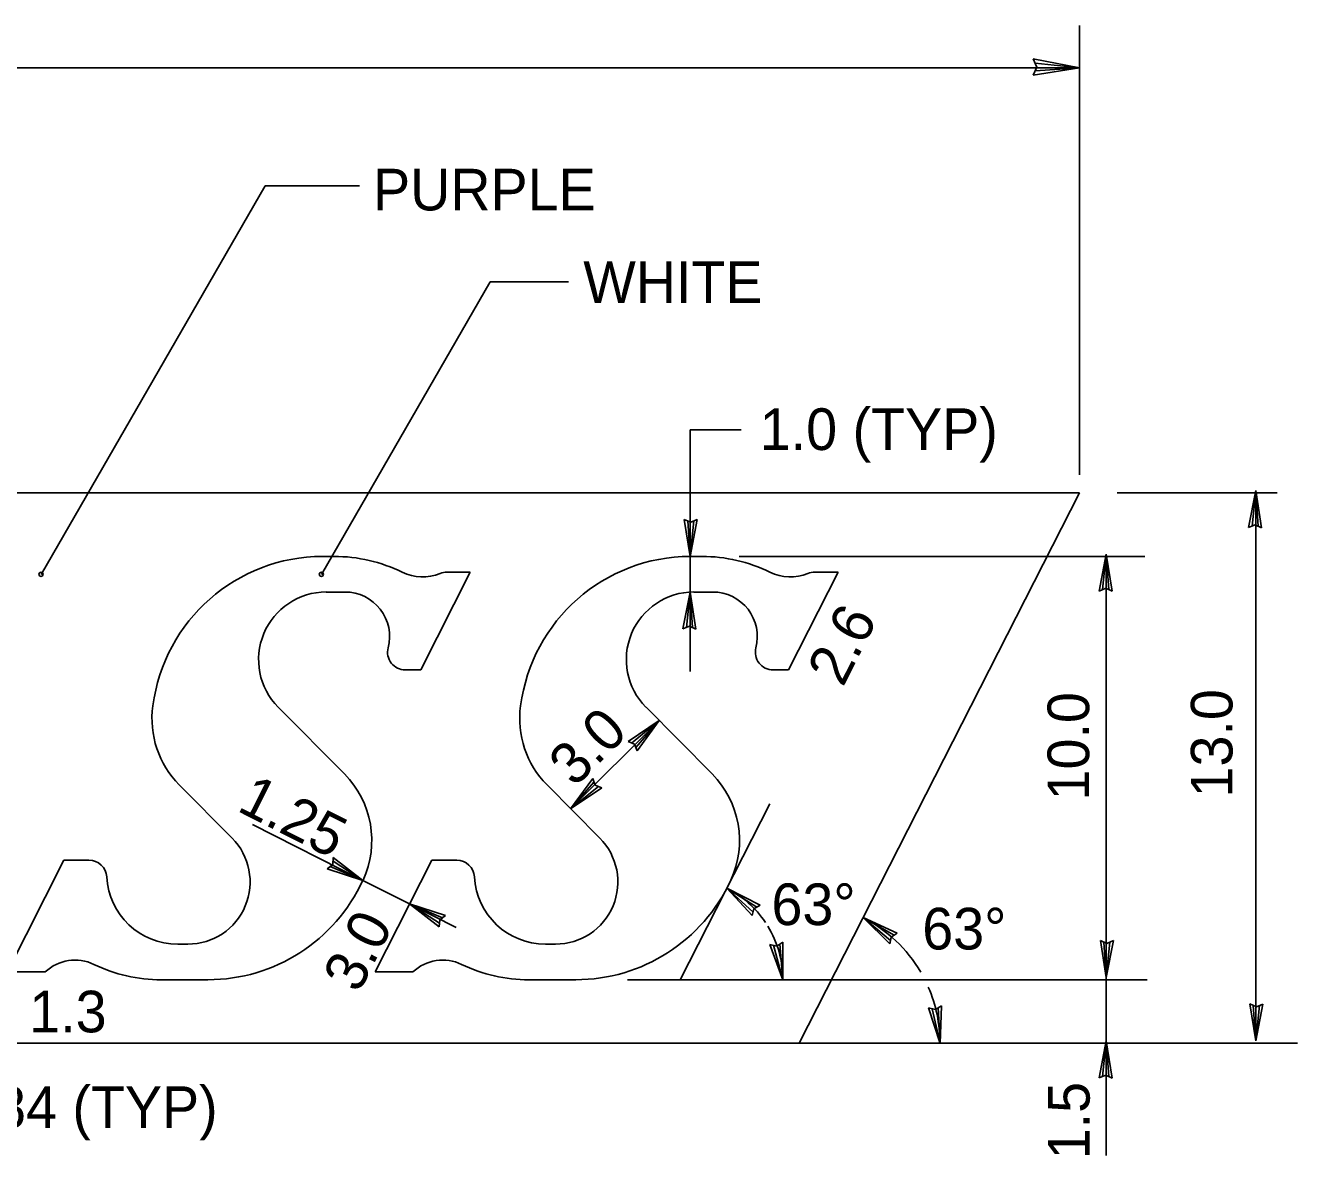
# Model space of a CAD drawing. Extents: x 10268197 to 10269179, y 2141503 to 2142677.
# Drawn here: x 10268499.02 to 10268520.42, y 2142087.31 to 2142106.32 of the extents above; entities that cross this region are included whole.
import ezdxf

# ---------------------------------------------------------------- set-up
doc = ezdxf.new("R2010")
doc.units = 0
for name, color, linetype in [('1', 7, 'Continuous'), ('20', 7, 'Continuous'), ('21', 7, 'Continuous')]:
    doc.layers.add(name, color=color, linetype=linetype)

msp = doc.modelspace()

# ---------------------------------------------------------------- linework, layer by layer
at = {"layer": '1'}
for p, q in [((10268487.142, 2142098.453), (10268516.747, 2142098.453)), ((10268512.032, 2142089.198), (10268516.747, 2142098.453)), ((10268504.011, 2142097.385), (10268504.209, 2142097.385)), ((10268510.198, 2142097.385), (10268510.397, 2142097.385)), ((10268506.5, 2142097.123), (10268505.669, 2142095.477)), ((10268506.108, 2142097.122), (10268506.5, 2142097.123)), ((10268512.688, 2142097.122), (10268511.856, 2142095.477)), ((10268512.296, 2142097.122), (10268512.688, 2142097.122)), ((10268504.075, 2142096.787), (10268504.394, 2142096.787)), ((10268510.262, 2142096.787), (10268510.581, 2142096.787)), ((10268505.669, 2142095.477), (10268505.408, 2142095.477)), ((10268511.856, 2142095.477), (10268511.594, 2142095.477)), ((10268503.267, 2142094.849), (10268504.382, 2142093.727)), ((10268509.456, 2142094.849), (10268510.57, 2142093.727)), ((10268502.491, 2142092.649), (10268501.604, 2142093.543)), ((10268508.678, 2142092.649), (10268507.791, 2142093.543)), ((10268498.713, 2142090.398), (10268499.663, 2142092.278)), ((10268499.663, 2142092.278), (10268500.084, 2142092.278)), ((10268504.901, 2142090.398), (10268505.851, 2142092.278)), ((10268505.851, 2142092.278), (10268506.271, 2142092.278)), ((10268501.748, 2142090.865), (10268501.577, 2142090.865)), ((10268507.936, 2142090.865), (10268507.764, 2142090.865)), ((10268499.348, 2142090.398), (10268498.713, 2142090.398)), ((10268505.536, 2142090.398), (10268504.901, 2142090.398)), ((10268502.086, 2142090.266), (10268501.299, 2142090.266)), ((10268508.274, 2142090.266), (10268507.486, 2142090.266)), ((10268486.559, 2142089.198), (10268512.032, 2142089.198))]:
    msp.add_line(p, q, dxfattribs=at)
for centre, radius, start, end in [((10268504.075, 2142095.651), 1.137, 90, 224.7881), ((10268504.394, 2142096.039), 0.748, 345.4379, 90), ((10268510.262, 2142095.651), 1.137, 90, 224.7881), ((10268510.581, 2142096.039), 0.748, 345.4379, 90), ((10268505.407, 2142095.776), 0.299, 165.4379, 270), ((10268511.595, 2142095.776), 0.299, 165.4379, 270), ((10268501.748, 2142091.912), 1.047, 270, 44.7784), ((10268507.935, 2142091.912), 1.047, 270, 44.7784), ((10268500.084, 2142091.979), 0.299, 3.1643, 90), ((10268506.271, 2142091.979), 0.299, 3.1643, 90), ((10268501.577, 2142092.061), 1.196, 183.1643, 270), ((10268507.764, 2142092.061), 1.196, 183.1643, 270)]:
    msp.add_arc(centre, radius, start, end, dxfattribs=at)
for centre, major_axis, start_param, end_param in [((10268504.011, 2142094.485), (0, 2.9), 0, 1.436562), ((10268504.209, 2142094.749), (0, 2.637), 5.830963, 6.283185), ((10268510.198, 2142094.485), (0, 2.9), 0, 1.436562), ((10268510.397, 2142094.749), (0, 2.637), 5.830963, 6.283185), ((10268505.696, 2142097.832), (0, 0.791), 2.68937, 3.526171), ((10268506.108, 2142096.805), (0, 0.316), 0, 0.384579), ((10268511.883, 2142097.832), (0, 0.791), 2.68937, 3.526171), ((10268512.296, 2142096.805), (0, 0.316), 0, 0.384579), ((10268502.714, 2142094.662), (0, 1.582), 1.436562, 2.356194), ((10268508.901, 2142094.662), (0, 1.582), 1.436562, 2.356194), ((10268503.272, 2142092.609), (0, -1.582), 1.133591, 2.356194), ((10268509.459, 2142092.609), (0, -1.582), 1.133591, 2.356194), ((10268502.086, 2142093.167), (0, -2.9), 0, 1.133591), ((10268508.274, 2142093.167), (0, -2.9), 0, 1.133591), ((10268499.85, 2142089.86), (0, -0.738), 2.69443, 3.895387), ((10268506.037, 2142089.86), (0, -0.738), 2.69443, 3.895387), ((10268501.299, 2142092.903), (0, -2.637), 5.836023, 6.283185), ((10268507.486, 2142092.903), (0, -2.637), 5.836023, 6.283185)]:
    msp.add_ellipse(centre, major_axis=major_axis, ratio=0.992614, start_param=start_param, end_param=end_param, dxfattribs=at)
at = {"layer": '20'}
for p, q in [((10268516.747, 2142099.165), (10268516.747, 2142106.315)), ((10268516.747, 2142105.604), (10268469.71, 2142105.604)), ((10268499.277, 2142097.084), (10268503.049, 2142103.617)), ((10268503.049, 2142103.617), (10268504.637, 2142103.617)), ((10268503.994, 2142097.084), (10268506.836, 2142102.006)), ((10268506.836, 2142102.006), (10268508.154, 2142102.006)), ((10268510.198, 2142099.515), (10268510.198, 2142097.386)), ((10268510.198, 2142099.515), (10268511.056, 2142099.515)), ((10268516.747, 2142098.76), (10268516.747, 2142099.165)), ((10268520.077, 2142098.453), (10268517.385, 2142098.453)), ((10268519.715, 2142089.237), (10268519.715, 2142098.492)), ((10268517.2, 2142090.304), (10268517.2, 2142097.424)), ((10268510.198, 2142097.386), (10268510.198, 2142096.785)), ((10268511.026, 2142097.386), (10268517.851, 2142097.386)), ((10268510.198, 2142096.785), (10268510.198, 2142095.453)), ((10268508.187, 2142093.143), (10268509.68, 2142094.624)), ((10268510.029, 2142090.266), (10268511.538, 2142093.227)), ((10268504.694, 2142091.938), (10268502.835, 2142092.878)), ((10268505.479, 2142091.541), (10268504.694, 2142091.938)), ((10268506.264, 2142091.145), (10268505.479, 2142091.541)), ((10268509.146, 2142090.266), (10268512.576, 2142090.266)), ((10268512.576, 2142090.266), (10268517.889, 2142090.266)), ((10268517.199, 2142089.237), (10268517.2, 2142090.304)), ((10268512.032, 2142089.198), (10268520.418, 2142089.198)), ((10268517.199, 2142087.31), (10268517.199, 2142089.237))]:
    msp.add_line(p, q, dxfattribs=at)
for centre in [(10268499.277, 2142097.084), (10268503.994, 2142097.084)]:
    msp.add_circle(centre, 0.0356, dxfattribs=at)
for centre, radius, start, end in [((10268510.029, 2142090.266), 1.73, 33.9529, 63.0014), ((10268512.032, 2142089.198), 2.37, 30.3328, 63.0012), ((10268510.029, 2142090.266), 1.73, 0, 31.4593), ((10268512.032, 2142089.198), 2.37, 360, 23.4794)]:
    msp.add_arc(centre, radius, start, end, dxfattribs=at)
at = {"layer": '21'}
for p, q in [((10268516.029, 2142105.616), (10268515.968, 2142105.48)), ((10268516.747, 2142105.604), (10268515.968, 2142105.48)), ((10268516.747, 2142105.604), (10268515.972, 2142105.754)), ((10268515.972, 2142105.754), (10268516.029, 2142105.616)), ((10268516.747, 2142105.604), (10268516.001, 2142105.551)), ((10268516.747, 2142105.604), (10268516.002, 2142105.682)), ((10268519.715, 2142098.492), (10268519.595, 2142097.872)), ((10268519.715, 2142098.492), (10268519.653, 2142097.896)), ((10268519.715, 2142098.492), (10268519.814, 2142097.868)), ((10268519.715, 2142098.492), (10268519.757, 2142097.895)), ((10268510.198, 2142097.386), (10268510.099, 2142098.009)), ((10268510.208, 2142097.96), (10268510.099, 2142098.009)), ((10268510.198, 2142097.386), (10268510.157, 2142097.983)), ((10268510.198, 2142097.386), (10268510.318, 2142098.005)), ((10268510.198, 2142097.386), (10268510.261, 2142097.982)), ((10268510.318, 2142098.005), (10268510.208, 2142097.96)), ((10268519.595, 2142097.872), (10268519.705, 2142097.918)), ((10268519.705, 2142097.918), (10268519.814, 2142097.868)), ((10268517.2, 2142097.424), (10268517.079, 2142096.804)), ((10268517.2, 2142097.424), (10268517.137, 2142096.828)), ((10268517.2, 2142097.424), (10268517.298, 2142096.8)), ((10268517.2, 2142097.424), (10268517.241, 2142096.827)), ((10268510.198, 2142096.785), (10268510.078, 2142096.166)), ((10268510.198, 2142096.785), (10268510.136, 2142096.189)), ((10268510.198, 2142096.785), (10268510.297, 2142096.162)), ((10268510.198, 2142096.785), (10268510.24, 2142096.188)), ((10268517.079, 2142096.804), (10268517.19, 2142096.85)), ((10268517.19, 2142096.85), (10268517.298, 2142096.8)), ((10268510.078, 2142096.166), (10268510.188, 2142096.211)), ((10268510.188, 2142096.211), (10268510.297, 2142096.162)), ((10268509.68, 2142094.624), (10268509.155, 2142094.273)), ((10268509.68, 2142094.624), (10268509.213, 2142094.248)), ((10268509.68, 2142094.624), (10268509.286, 2142094.174)), ((10268509.68, 2142094.624), (10268509.307, 2142094.115)), ((10268509.155, 2142094.273), (10268509.265, 2142094.227)), ((10268509.265, 2142094.227), (10268509.307, 2142094.115)), ((10268508.187, 2142093.143), (10268508.561, 2142093.653)), ((10268508.187, 2142093.143), (10268508.582, 2142093.594)), ((10268508.602, 2142093.541), (10268508.561, 2142093.653)), ((10268508.187, 2142093.143), (10268508.654, 2142093.519)), ((10268508.187, 2142093.143), (10268508.712, 2142093.494)), ((10268508.712, 2142093.494), (10268508.602, 2142093.541)), ((10268504.195, 2142092.325), (10268504.186, 2142092.206)), ((10268504.694, 2142091.938), (10268504.195, 2142092.325)), ((10268504.186, 2142092.206), (10268504.093, 2142092.131)), ((10268504.694, 2142091.938), (10268504.093, 2142092.131)), ((10268504.694, 2142091.938), (10268504.142, 2142092.17)), ((10268504.694, 2142091.938), (10268504.19, 2142092.263)), ((10268510.815, 2142091.809), (10268511.376, 2142091.52)), ((10268510.815, 2142091.809), (10268511.243, 2142091.345)), ((10268510.815, 2142091.809), (10268511.259, 2142091.406)), ((10268510.815, 2142091.809), (10268511.321, 2142091.489)), ((10268505.479, 2142091.541), (10268506.08, 2142091.348)), ((10268505.479, 2142091.541), (10268505.978, 2142091.154)), ((10268505.479, 2142091.541), (10268505.983, 2142091.217)), ((10268505.479, 2142091.541), (10268506.031, 2142091.309)), ((10268511.243, 2142091.345), (10268511.272, 2142091.461)), ((10268511.272, 2142091.461), (10268511.376, 2142091.52)), ((10268505.978, 2142091.154), (10268505.987, 2142091.273)), ((10268505.987, 2142091.273), (10268506.08, 2142091.348)), ((10268513.108, 2142091.311), (10268513.683, 2142091.049)), ((10268513.108, 2142091.311), (10268513.559, 2142090.868)), ((10268513.108, 2142091.311), (10268513.571, 2142090.929)), ((10268513.108, 2142091.311), (10268513.629, 2142091.016)), ((10268513.582, 2142090.985), (10268513.683, 2142091.049)), ((10268511.76, 2142090.268), (10268511.542, 2142090.861)), ((10268511.658, 2142090.833), (10268511.542, 2142090.861)), ((10268511.76, 2142090.268), (10268511.603, 2142090.846)), ((10268511.758, 2142090.899), (10268511.658, 2142090.833)), ((10268511.76, 2142090.268), (10268511.705, 2142090.865)), ((10268511.76, 2142090.268), (10268511.758, 2142090.899)), ((10268513.559, 2142090.868), (10268513.582, 2142090.985)), ((10268517.2, 2142090.304), (10268517.101, 2142090.928)), ((10268517.21, 2142090.878), (10268517.101, 2142090.928)), ((10268517.2, 2142090.304), (10268517.158, 2142090.901)), ((10268517.2, 2142090.304), (10268517.32, 2142090.924)), ((10268517.2, 2142090.304), (10268517.262, 2142090.9)), ((10268517.32, 2142090.924), (10268517.21, 2142090.878)), ((10268514.404, 2142089.196), (10268514.209, 2142089.796)), ((10268514.324, 2142089.764), (10268514.209, 2142089.796)), ((10268514.404, 2142089.196), (10268514.27, 2142089.779)), ((10268514.426, 2142089.827), (10268514.324, 2142089.764)), ((10268514.404, 2142089.196), (10268514.373, 2142089.794)), ((10268514.404, 2142089.196), (10268514.426, 2142089.827)), ((10268519.715, 2142089.237), (10268519.616, 2142089.86)), ((10268519.725, 2142089.811), (10268519.616, 2142089.86)), ((10268519.715, 2142089.237), (10268519.673, 2142089.834)), ((10268519.715, 2142089.237), (10268519.835, 2142089.857)), ((10268519.715, 2142089.237), (10268519.777, 2142089.833)), ((10268519.835, 2142089.857), (10268519.725, 2142089.811)), ((10268517.199, 2142089.237), (10268517.079, 2142088.617)), ((10268517.199, 2142089.237), (10268517.137, 2142088.641)), ((10268517.199, 2142089.237), (10268517.298, 2142088.613)), ((10268517.199, 2142089.237), (10268517.241, 2142088.64)), ((10268517.079, 2142088.617), (10268517.19, 2142088.663)), ((10268517.19, 2142088.663), (10268517.298, 2142088.613))]:
    msp.add_line(p, q, dxfattribs=at)

# ---------------------------------------------------------------- texts
at = {"layer": '20'}
for s, p in [('PURPLE', (10268504.864, 2142103.205)), ('WHITE', (10268508.401, 2142101.647)), ('1.0 (TYP)', (10268511.37, 2142099.176)), ('63°', (10268511.567, 2142091.186)), ('63°', (10268514.104, 2142090.776)), ('1.3', (10268499.079, 2142089.382)), ('.84 (TYP)', (10268498.244, 2142087.774))]:
    msp.add_text(s, height=0.7, dxfattribs=at).set_placement(p)
for s, rotation, p in [('2.6', 63.1678, (10268512.768, 2142095.172)), ('13.0', 90, (10268519.323, 2142093.332)), ('10.0', 90, (10268516.912, 2142093.282)), ('3.0', 44.7737, (10268508.254, 2142093.489)), ('1.25', 333.1861, (10268502.554, 2142093.117)), ('3.0', 63.1839, (10268504.621, 2142090.022)), ('1.5', 90, (10268516.92, 2142087.247))]:
    msp.add_text(s, height=0.7, rotation=rotation, dxfattribs=at).set_placement(p)

doc.saveas('drawing.dxf')
